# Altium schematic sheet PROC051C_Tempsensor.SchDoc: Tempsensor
size 431 x 279 mm; Date: Not shown in title block; ApprovedBy: Not shown in title block; CheckedBy: Not shown in title block; Author: Not shown in title block; CompanyName: Not shown in title block; Engineer: Not shown in title block; Organization: Not shown in title block; Address1: Not shown in title block; Address2: Not shown in title block; Address3: Not shown in title block; Address4: Not shown in title block; DocumentNumber: 15; Revision: Use project parameter SCH_Rev; SheetNumber: 15; SheetTotal: 16; PageSetup: Record=PageOptions¦CenterHorizontal=True¦CenterVertical=True¦PrintScale=1.00¦XCorrection=1.00¦YCorrection=1.00¦PrintKind=0¦BorderSize=5000000¦LeftOffset=0¦BottomOffset=0¦Orientation=2¦PaperLength=1000¦PaperWidth=1000¦Scale=100¦PaperSource=15¦PrintQuality=600¦MediaType=1¦DitherType=10¦PaperKind=Letter¦PrintScaleMode=1
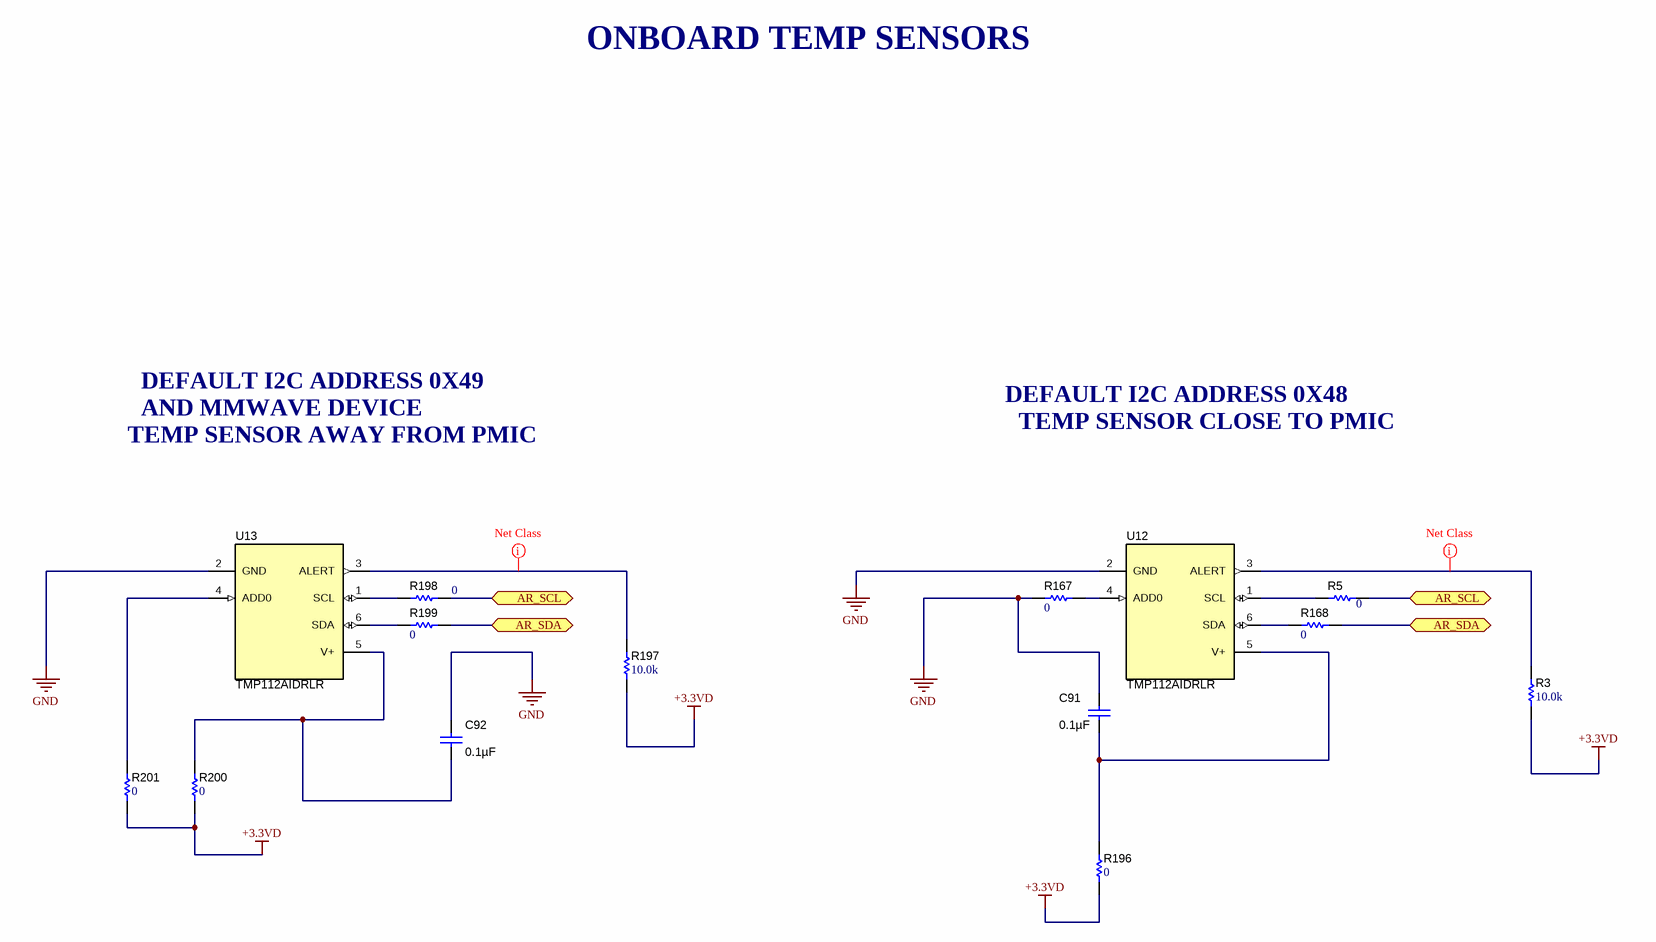
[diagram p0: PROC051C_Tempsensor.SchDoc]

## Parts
C91  ValueDisplayed: 0.1µF  [0402L]  (hidden comment: C0402C104K8RACTU)
C92  ValueDisplayed: 0.1µF  [0402L]  (hidden comment: C0402C104K8RACTU)
R3  ValueDisplayed: 10.0k  [0402L]  (hidden comment: CRCW040210K0FKED)
R5  ValueDisplayed: 0  [0201_Silk]  (hidden comment: CRCW02010000Z0ED)
R167  ValueDisplayed: 0  [0201_Silk]  (hidden comment: CRCW02010000Z0ED)
R168  ValueDisplayed: 0  [0201_Silk]  (hidden comment: CRCW02010000Z0ED)
R196  ValueDisplayed: 0  [0402L]  (hidden comment: ERJ-2GE0R00X)
R197  ValueDisplayed: 10.0k  [0402L]  (hidden comment: CRCW040210K0FKED)
R198  ValueDisplayed: 0  [0201_Silk]  (hidden comment: CRCW02010000Z0ED)
R199  ValueDisplayed: 0  [0201_Silk]  (hidden comment: CRCW02010000Z0ED)
R200  ValueDisplayed: 0  [0402L]  (hidden comment: ERJ-2GE0R00X)
R201  ValueDisplayed: 0  [0201_Silk]  (hidden comment: CRCW02010000Z0ED)
U12  TMP112AIDRLR  [DRL0006A]
U13  TMP112AIDRLR  [DRL0006A]

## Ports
AR_SCL, AR_SDA

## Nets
+3.3VD: R3.2 R196.2 R197.2 R200.2 R201.2
GND: C91.1 C92.1 R167.1 U12.2(GND) U13.2(GND)
AR_SCL: R5.1 R198.1 ; port AR_SCL
AR_SDA: R168.2 R199.2 ; port AR_SDA
NetC91_2: C91.2 R196.1 U12.5(V+)
NetC92_2: C92.2 R200.1 U13.5(V+)
NetR3_1: R3.1 U12.3(ALERT)
NetR5_2: R5.2 U12.1(SCL)
NetR167_2: R167.2 U12.4(ADD0)
NetR168_1: R168.1 U12.6(SDA)
NetR197_1: R197.1 U13.3(ALERT)
NetR198_2: R198.2 U13.1(SCL)
NetR199_1: R199.1 U13.6(SDA)
NetR201_1: R201.1 U13.4(ADD0)

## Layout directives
net class PWR: NetR3_1, NetR197_1

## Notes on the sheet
- ONBOARD TEMP SENSORS
- DEFAULT I2C ADDRESS 0X49
- DEFAULT I2C ADDRESS 0X48
- TEMP SENSOR AWAY FROM PMIC
- AND MMWAVE DEVICE
- TEMP SENSOR CLOSE TO PMIC

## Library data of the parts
C91 C92 = CMP-0078241-1: CAP, CERM, 0.1 µF, 10 V,+/- 10%, X7R, 0402; Manufacturer: Kemet; TaMin_C: -55°C; Polarized: N; SizeAreaWB_mm2: 3; U/M: EA; Value: 0.1uF; TaMax_C: 125°C; SizeZ_mm: 0.6; SizeX_mm: 1; SizeY_mm: 0.5; Cap_Case: 0402; Value2: 10V; Cap_F: 100nF; AEC Category: Q200
R3 R197 = CMP-0025958-3: RES, 10.0 k, 1%, 0.063 W, AEC-Q200 Grade 0, 0402; Manufacturer: Vishay-Dale; Power_W: 63mW; TempCo: 100 ppm/C; Value_Code: 10k0; Value: 10.0k; EIA_Code: E96; Res_ohm: 10k; SizeX_mm: 1; SizeY_mm: 0.5; SizeZ_mm: 0.6; Value2: 0.063W; AEC Qualified: Y; VDC_V: 50V; AEC Category: Q200; AEC Grade: 0
R5 R167 R168 R198 R199 R201 = CMP-0027008-4: RES, 0, 5%, 0.05 W, 0201; Manufacturer: Vishay-Dale; Power_W: 50mW; TempCo: ppm/C; Value_Code: 0000; Value: 0; EIA_Code: E24; SizeX_mm: 0.6; SizeY_mm: 0.3; SizeZ_mm: 0.26; Value2: 0.05W; SizeArea_mm2: 0.18; AEC Qualified: N; AEC Category: Q200
R196 R200 = CMP-0026992-3: RES, 0, 5%, 0.1 W, AEC-Q200 Grade 0, 0402; Manufacturer: Panasonic; Power_W: 100mW; TempCo: 600 ppm/C; Value_Code: 0000; Value: 0; EIA_Code: E24; SizeX_mm: 1; SizeY_mm: 0.5; SizeZ_mm: 0.6; Value2: 0.1W; AEC Qualified: Y; VDC_V: 50V; AEC Category: Q200; SizeAreaWB_mm2: 3
U12 U13 = CMP-0067397-2: 1.4V-Capable +/-0.5degC Temperature Sensor with Alert Function and I2C/SMBus interface in SOT-563, DRL0006A (SOT-OTHER-6); Alternate PartNumber: TMP112AIDRLT; Alternate Manufacturer: Texas Instruments; Green_Lifecycle: Active; SizeAreaWB_mm2: 6.76; Green_REACh: Passed; U/M: EA; SizeZ_mm: 0.6; SizeX_mm: 1.6; SizeArea_mm2: 2.56; CompType: IC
